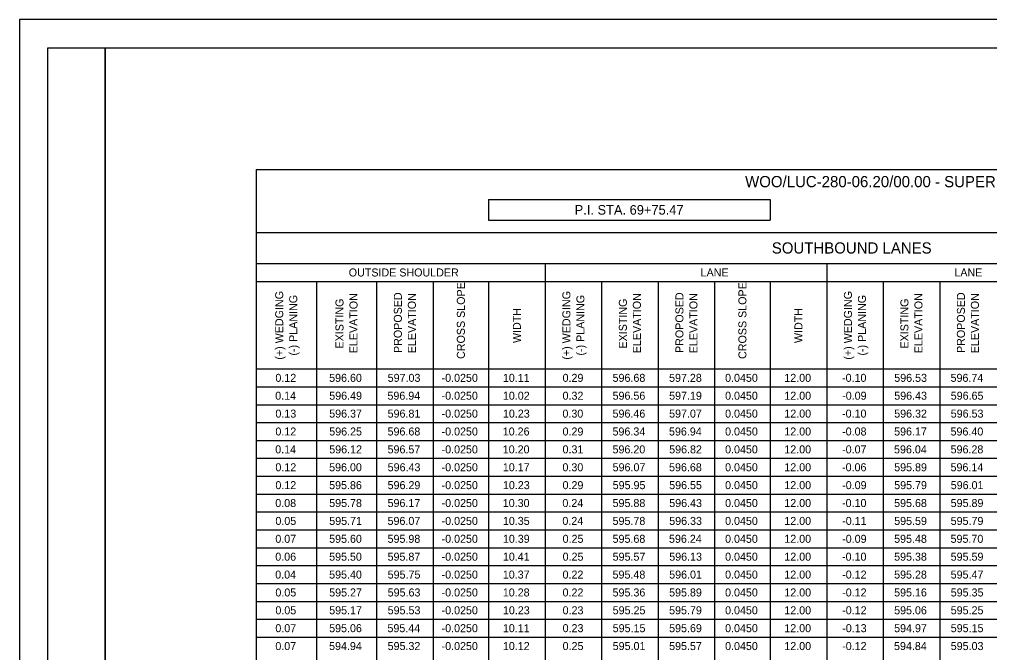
# Model space of a CAD drawing. Extents: x 0 to 34, y 0 to 22.
# Drawn here: x 0 to 16.97, y 10.92 to 22 of the extents above; entities that cross this region are included whole.
import ezdxf

# ---------------------------------------------------------------- set-up
doc = ezdxf.new("R2010")
doc.units = 0
for name, color, linetype in [('SH_Border', 7, 'Continuous'), ('SH_Cut_Line', 7, 'Continuous'), ('SH_Text', 7, 'Continuous')]:
    doc.layers.add(name, color=color, linetype=linetype)

msp = doc.modelspace()

# ---------------------------------------------------------------- linework, layer by layer
at = {"layer": 'SH_Border'}
for points in [[(0.5, 21.5), (1.5, 21.5), (1.5, 0.5), (0.5, 0.5)], [(1.5, 21.5), (33.5, 21.5), (33.5, 0.5), (1.5, 0.5)]]:
    msp.add_lwpolyline(points, close=True, dxfattribs=at)
at = {"layer": 'SH_Cut_Line'}
msp.add_lwpolyline([(0, 0), (34, 0), (34, 22), (0, 22)], close=True, dxfattribs=at)
at = {"layer": 'SH_Text'}
for p, q in [((4.14, 19.375), (29.356, 19.375)), ((4.14, 19.375), (4.14, 2.624)), ((8.208, 18.848), (13.133, 18.848)), ((8.208, 18.848), (8.208, 18.486)), ((13.133, 18.848), (13.133, 18.486)), ((8.208, 18.486), (13.133, 18.486)), ((4.14, 18.271), (29.356, 18.271)), ((4.14, 17.728), (29.356, 17.728)), ((9.196, 17.728), (9.196, 2.624)), ((14.121, 17.728), (14.121, 2.624)), ((4.14, 17.415), (24.942, 17.415)), ((5.194, 17.415), (5.194, 2.624)), ((6.248, 17.415), (6.248, 2.624)), ((7.236, 17.415), (7.236, 2.624)), ((8.208, 17.415), (8.208, 2.624)), ((10.185, 17.415), (10.185, 2.624)), ((11.173, 17.415), (11.173, 2.624)), ((12.161, 17.415), (12.161, 2.624)), ((13.133, 17.415), (13.133, 2.624)), ((15.109, 17.415), (15.109, 2.624)), ((16.098, 17.415), (16.098, 2.624)), ((4.14, 15.883), (29.356, 15.883)), ((4.14, 15.57), (29.356, 15.57)), ((4.14, 15.257), (29.356, 15.257)), ((4.14, 14.944), (29.356, 14.944)), ((4.14, 14.631), (29.356, 14.631)), ((4.14, 14.319), (29.356, 14.319)), ((4.14, 14.006), (29.356, 14.006)), ((4.14, 13.693), (29.356, 13.693)), ((4.14, 13.38), (29.356, 13.38)), ((4.14, 13.067), (29.356, 13.067)), ((4.14, 12.754), (29.356, 12.754)), ((4.14, 12.441), (29.356, 12.441)), ((4.14, 12.128), (29.356, 12.128)), ((4.14, 11.815), (29.356, 11.815)), ((4.14, 11.502), (29.356, 11.502)), ((4.14, 11.189), (29.356, 11.189))]:
    msp.add_line(p, q, dxfattribs=at)

# ---------------------------------------------------------------- texts
for s, height, p in [('WOO/LUC-280-06.20/00.00 - SUPERELEVATION TABLE', 0.196, (12.694, 19.063)), ('P.I. STA. 69+75.47', 0.168, (9.713, 18.583)), ('SOUTHBOUND LANES', 0.196, (13.161, 17.902)), ('OUTSIDE SHOULDER', 0.14, (5.761, 17.501)), ('LANE', 0.14, (11.916, 17.501)), ('LANE', 0.14, (16.355, 17.501)), ('0.12', 0.14, (4.478, 15.657)), ('596.60', 0.14, (5.418, 15.657)), ('597.03', 0.14, (6.442, 15.657)), ('-0.0250', 0.14, (7.385, 15.657)), ('10.11', 0.14, (8.457, 15.657)), ('0.29', 0.14, (9.501, 15.657)), ('596.68', 0.14, (10.376, 15.657)), ('597.28', 0.14, (11.364, 15.657)), ('0.0450', 0.14, (12.344, 15.657)), ('12.00', 0.14, (13.38, 15.657)), ('-0.10', 0.14, (14.39, 15.657)), ('596.53', 0.14, (15.303, 15.657)), ('596.74', 0.14, (16.288, 15.657)), ('0.14', 0.14, (4.475, 15.344)), ('596.49', 0.14, (5.42, 15.344)), ('596.94', 0.14, (6.438, 15.344)), ('-0.0250', 0.14, (7.385, 15.344)), ('10.02', 0.14, (8.457, 15.344)), ('0.32', 0.14, (9.501, 15.344)), ('596.56', 0.14, (10.376, 15.344)), ('597.19', 0.14, (11.365, 15.344)), ('0.0450', 0.14, (12.344, 15.344)), ('12.00', 0.14, (13.38, 15.344)), ('-0.09', 0.14, (14.392, 15.344)), ('596.43', 0.14, (15.303, 15.344)), ('596.65', 0.14, (16.291, 15.344)), ('0.13', 0.14, (4.478, 15.031)), ('596.37', 0.14, (5.419, 15.031)), ('596.81', 0.14, (6.441, 15.031)), ('-0.0250', 0.14, (7.385, 15.031)), ('10.23', 0.14, (8.458, 15.031)), ('0.30', 0.14, (9.499, 15.031)), ('596.46', 0.14, (10.376, 15.031)), ('597.07', 0.14, (11.365, 15.031)), ('0.0450', 0.14, (12.344, 15.031)), ('12.00', 0.14, (13.38, 15.031)), ('-0.10', 0.14, (14.39, 15.031)), ('596.32', 0.14, (15.302, 15.031)), ('596.53', 0.14, (16.291, 15.031)), ('0.12', 0.14, (4.478, 14.718)), ('596.25', 0.14, (5.42, 14.718)), ('596.68', 0.14, (6.44, 14.718)), ('-0.0250', 0.14, (7.385, 14.718)), ('10.26', 0.14, (8.455, 14.718)), ('0.29', 0.14, (9.501, 14.718)), ('596.34', 0.14, (10.375, 14.718)), ('596.94', 0.14, (11.363, 14.718)), ('0.0450', 0.14, (12.344, 14.718)), ('12.00', 0.14, (13.38, 14.718)), ('-0.08', 0.14, (14.391, 14.718)), ('596.17', 0.14, (15.301, 14.718)), ('596.40', 0.14, (16.288, 14.718)), ('0.14', 0.14, (4.475, 14.405)), ('596.12', 0.14, (5.42, 14.405)), ('596.57', 0.14, (6.44, 14.405)), ('-0.0250', 0.14, (7.385, 14.405)), ('10.20', 0.14, (8.455, 14.405)), ('0.31', 0.14, (9.501, 14.405)), ('596.20', 0.14, (10.375, 14.405)), ('596.82', 0.14, (11.366, 14.405)), ('0.0450', 0.14, (12.344, 14.405)), ('12.00', 0.14, (13.38, 14.405)), ('-0.07', 0.14, (14.391, 14.405)), ('596.04', 0.14, (15.299, 14.405)), ('596.28', 0.14, (16.289, 14.405)), ('0.12', 0.14, (4.478, 14.092)), ('596.00', 0.14, (5.418, 14.092)), ('596.43', 0.14, (6.442, 14.092)), ('-0.0250', 0.14, (7.385, 14.092)), ('10.17', 0.14, (8.456, 14.092)), ('0.30', 0.14, (9.499, 14.092)), ('596.07', 0.14, (10.377, 14.092)), ('596.68', 0.14, (11.364, 14.092)), ('0.0450', 0.14, (12.344, 14.092)), ('12.00', 0.14, (13.38, 14.092)), ('-0.06', 0.14, (14.39, 14.092)), ('595.89', 0.14, (15.302, 14.092)), ('596.14', 0.14, (16.288, 14.092)), ('0.12', 0.14, (4.478, 13.779)), ('595.86', 0.14, (5.418, 13.779)), ('596.29', 0.14, (6.441, 13.779)), ('-0.0250', 0.14, (7.385, 13.779)), ('10.23', 0.14, (8.458, 13.779)), ('0.29', 0.14, (9.501, 13.779)), ('595.95', 0.14, (10.378, 13.779)), ('596.55', 0.14, (11.366, 13.779)), ('0.0450', 0.14, (12.344, 13.779)), ('12.00', 0.14, (13.38, 13.779)), ('-0.09', 0.14, (14.392, 13.779)), ('595.79', 0.14, (15.302, 13.779)), ('596.01', 0.14, (16.291, 13.779)), ('0.08', 0.14, (4.476, 13.466)), ('595.78', 0.14, (5.419, 13.466)), ('596.17', 0.14, (6.44, 13.466)), ('-0.0250', 0.14, (7.385, 13.466)), ('10.30', 0.14, (8.455, 13.466)), ('0.24', 0.14, (9.498, 13.466)), ('595.88', 0.14, (10.376, 13.466)), ('596.43', 0.14, (11.367, 13.466)), ('0.0450', 0.14, (12.344, 13.466)), ('12.00', 0.14, (13.38, 13.466)), ('-0.10', 0.14, (14.39, 13.466)), ('595.68', 0.14, (15.301, 13.466)), ('595.89', 0.14, (16.29, 13.466)), ('0.05', 0.14, (4.478, 13.153)), ('595.71', 0.14, (5.42, 13.153)), ('596.07', 0.14, (6.44, 13.153)), ('-0.0250', 0.14, (7.385, 13.153)), ('10.35', 0.14, (8.457, 13.153)), ('0.24', 0.14, (9.498, 13.153)), ('595.78', 0.14, (10.376, 13.153)), ('596.33', 0.14, (11.367, 13.153)), ('0.0450', 0.14, (12.344, 13.153)), ('12.00', 0.14, (13.38, 13.153)), ('-0.11', 0.14, (14.392, 13.153)), ('595.59', 0.14, (15.302, 13.153)), ('595.79', 0.14, (16.29, 13.153)), ('0.07', 0.14, (4.477, 12.84)), ('595.60', 0.14, (5.418, 12.84)), ('595.98', 0.14, (6.44, 12.84)), ('-0.0250', 0.14, (7.385, 12.84)), ('10.39', 0.14, (8.457, 12.84)), ('0.25', 0.14, (9.502, 12.84)), ('595.68', 0.14, (10.376, 12.84)), ('596.24', 0.14, (11.363, 12.84)), ('0.0450', 0.14, (12.344, 12.84)), ('12.00', 0.14, (13.38, 12.84)), ('-0.09', 0.14, (14.392, 12.84)), ('595.48', 0.14, (15.301, 12.84)), ('595.70', 0.14, (16.288, 12.84)), ('0.06', 0.14, (4.476, 12.527)), ('595.50', 0.14, (5.418, 12.527)), ('595.87', 0.14, (6.44, 12.527)), ('-0.0250', 0.14, (7.385, 12.527)), ('10.41', 0.14, (8.457, 12.527)), ('0.25', 0.14, (9.502, 12.527)), ('595.57', 0.14, (10.377, 12.527)), ('596.13', 0.14, (11.367, 12.527)), ('0.0450', 0.14, (12.344, 12.527)), ('12.00', 0.14, (13.38, 12.527)), ('-0.10', 0.14, (14.39, 12.527)), ('595.38', 0.14, (15.301, 12.527)), ('595.59', 0.14, (16.29, 12.527)), ('0.04', 0.14, (4.475, 12.214)), ('595.40', 0.14, (5.418, 12.214)), ('595.75', 0.14, (6.442, 12.214)), ('-0.0250', 0.14, (7.385, 12.214)), ('10.37', 0.14, (8.456, 12.214)), ('0.22', 0.14, (9.501, 12.214)), ('595.48', 0.14, (10.376, 12.214)), ('596.01', 0.14, (11.366, 12.214)), ('0.0450', 0.14, (12.344, 12.214)), ('12.00', 0.14, (13.38, 12.214)), ('-0.12', 0.14, (14.392, 12.214)), ('595.28', 0.14, (15.301, 12.214)), ('595.47', 0.14, (16.29, 12.214)), ('0.05', 0.14, (4.478, 11.901)), ('595.27', 0.14, (5.419, 11.901)), ('595.63', 0.14, (6.442, 11.901)), ('-0.0250', 0.14, (7.385, 11.901)), ('10.28', 0.14, (8.456, 11.901)), ('0.22', 0.14, (9.501, 11.901)), ('595.36', 0.14, (10.376, 11.901)), ('595.89', 0.14, (11.365, 11.901)), ('0.0450', 0.14, (12.344, 11.901)), ('12.00', 0.14, (13.38, 11.901)), ('-0.12', 0.14, (14.392, 11.901)), ('595.16', 0.14, (15.301, 11.901)), ('595.35', 0.14, (16.291, 11.901)), ('0.05', 0.14, (4.478, 11.589)), ('595.17', 0.14, (5.419, 11.589)), ('595.53', 0.14, (6.442, 11.589)), ('-0.0250', 0.14, (7.385, 11.589)), ('10.23', 0.14, (8.458, 11.589)), ('0.23', 0.14, (9.502, 11.589)), ('595.25', 0.14, (10.378, 11.589)), ('595.79', 0.14, (11.365, 11.589)), ('0.0450', 0.14, (12.344, 11.589)), ('12.00', 0.14, (13.38, 11.589)), ('-0.12', 0.14, (14.392, 11.589)), ('595.06', 0.14, (15.301, 11.589)), ('595.25', 0.14, (16.291, 11.589)), ('0.07', 0.14, (4.477, 11.276)), ('595.06', 0.14, (5.418, 11.276)), ('595.44', 0.14, (6.438, 11.276)), ('-0.0250', 0.14, (7.385, 11.276)), ('10.11', 0.14, (8.457, 11.276)), ('0.23', 0.14, (9.502, 11.276)), ('595.15', 0.14, (10.378, 11.276)), ('595.69', 0.14, (11.365, 11.276)), ('0.0450', 0.14, (12.344, 11.276)), ('12.00', 0.14, (13.38, 11.276)), ('-0.13', 0.14, (14.393, 11.276)), ('594.97', 0.14, (15.301, 11.276)), ('595.15', 0.14, (16.291, 11.276)), ('0.07', 0.14, (4.477, 10.963)), ('594.94', 0.14, (5.417, 10.963)), ('595.32', 0.14, (6.441, 10.963)), ('-0.0250', 0.14, (7.385, 10.963)), ('10.12', 0.14, (8.457, 10.963)), ('0.25', 0.14, (9.502, 10.963)), ('595.01', 0.14, (10.378, 10.963)), ('595.57', 0.14, (11.365, 10.963)), ('0.0450', 0.14, (12.344, 10.963)), ('12.00', 0.14, (13.38, 10.963)), ('-0.12', 0.14, (14.392, 10.963)), ('594.84', 0.14, (15.299, 10.963)), ('595.03', 0.14, (16.291, 10.963))]:
    msp.add_text(s, height=height, dxfattribs=at).set_placement(p)
for s, p in [('CROSS SLOPE', (7.792, 16.058)), ('CROSS SLOPE', (12.717, 16.058)), ('(+) WEDGING', (4.615, 16.045)), ('(-) PLANING', (4.86, 16.117)), ('ELEVATION', (5.914, 16.158)), ('PROPOSED ', (6.69, 16.162)), ('ELEVATION', (6.935, 16.158)), ('(+) WEDGING', (9.638, 16.045)), ('(-) PLANING', (9.883, 16.117)), ('ELEVATION', (10.871, 16.158)), ('PROPOSED ', (11.615, 16.162)), ('ELEVATION', (11.86, 16.158)), ('(+) WEDGING', (14.563, 16.045)), ('(-) PLANING', (14.808, 16.117)), ('ELEVATION', (15.796, 16.158)), ('PROPOSED ', (16.539, 16.162)), ('ELEVATION', (16.784, 16.158)), ('EXISTING ', (5.669, 16.24)), ('EXISTING ', (10.626, 16.24)), ('EXISTING ', (15.551, 16.24)), ('WIDTH', (8.772, 16.336)), ('WIDTH', (13.697, 16.336))]:
    msp.add_text(s, height=0.14, rotation=90, dxfattribs=at).set_placement(p)

doc.saveas('drawing.dxf')
